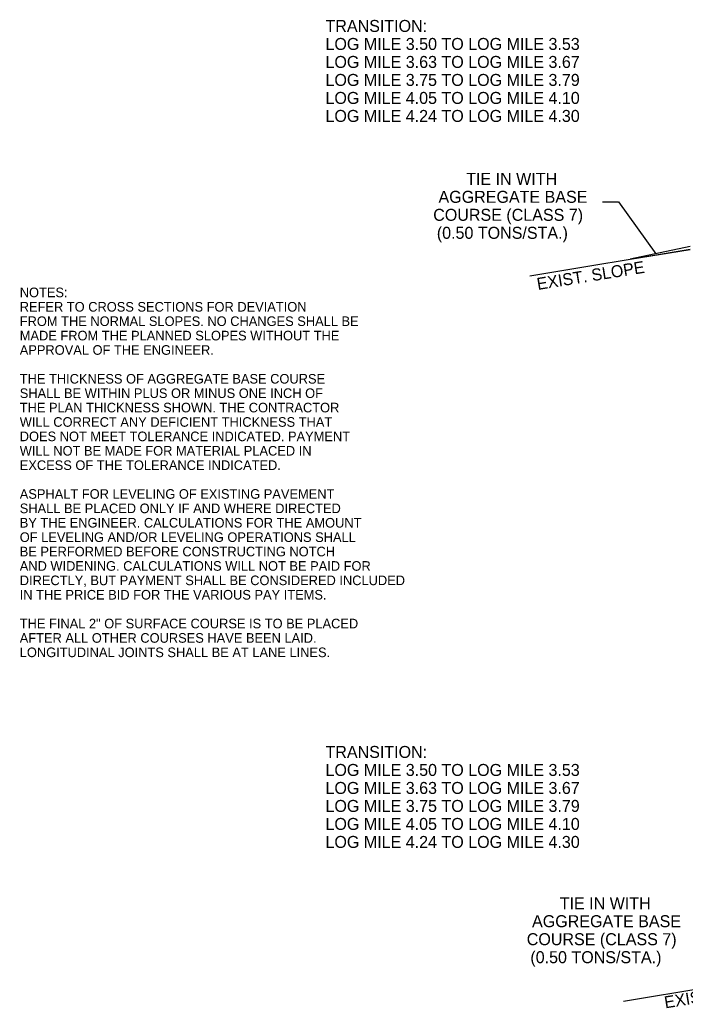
# Model space of a CAD drawing. Extents: x 542112 to 1930787, y -1968972 to 596640.
# Drawn here: x 546302 to 546718, y -1946810 to -1946192 of the extents above; entities that cross this region are included whole.
import ezdxf

# ---------------------------------------------------------------- set-up
doc = ezdxf.new("R2010")
doc.units = 0
doc.layers.add('Default', color=7, linetype='Continuous')
doc.layers.add('R_Draft', color=7, linetype='Continuous')

msp = doc.modelspace()

# ---------------------------------------------------------------- linework, layer by layer
at = {"layer": 'R_Draft'}
for p, q in [((546721.36, -1946335.6), (546621.29, -1946352.28)), ((546721.36, -1946333.9), (546683.86, -1946341.84)), ((546683.86, -1946341.84), (546721.36, -1946335.6)), ((546779.81, -1946789.04), (546679.74, -1946805.71))]:
    msp.add_line(p, q, dxfattribs=at)
msp.add_lwpolyline([(546666.51, -1946305.99), (546676.51, -1946305.99), (546699.84, -1946338.49)], dxfattribs=at)

# ---------------------------------------------------------------- texts
at = {"layer": 'Default'}
for s, p in [('NOTES:', (546302.45, -1946365.52)), ('REFER TO CROSS SECTIONS FOR DEVIATION', (546302.45, -1946374.52)), ('FROM THE NORMAL SLOPES. NO CHANGES SHALL BE', (546302.45, -1946383.52)), ('MADE FROM THE PLANNED SLOPES WITHOUT THE', (546302.45, -1946392.52)), ('APPROVAL OF THE ENGINEER.', (546302.45, -1946401.52)), ('THE THICKNESS OF AGGREGATE BASE COURSE', (546302.45, -1946419.52)), ('SHALL BE WITHIN PLUS OR MINUS ONE INCH OF', (546302.45, -1946428.52)), ('THE PLAN THICKNESS SHOWN. THE CONTRACTOR', (546302.45, -1946437.52)), ('WILL CORRECT ANY DEFICIENT THICKNESS THAT', (546302.45, -1946446.52)), ('DOES NOT MEET TOLERANCE INDICATED. PAYMENT', (546302.45, -1946455.52)), ('WILL NOT BE MADE FOR MATERIAL PLACED IN', (546302.45, -1946464.52)), ('EXCESS OF THE TOLERANCE INDICATED.', (546302.45, -1946473.52)), ('ASPHALT FOR LEVELING OF EXISTING PAVEMENT', (546302.45, -1946491.52)), ('SHALL BE PLACED ONLY IF AND WHERE DIRECTED', (546302.45, -1946500.52)), ('BY THE ENGINEER. CALCULATIONS FOR THE AMOUNT', (546302.45, -1946509.52)), ('OF LEVELING AND/OR LEVELING OPERATIONS SHALL', (546302.45, -1946518.52)), ('BE PERFORMED BEFORE CONSTRUCTING NOTCH', (546302.45, -1946527.52)), ('AND WIDENING. CALCULATIONS WILL NOT BE PAID FOR', (546302.45, -1946536.52)), ('DIRECTLY, BUT PAYMENT SHALL BE CONSIDERED INCLUDED', (546302.45, -1946545.52)), ('IN THE PRICE BID FOR THE VARIOUS PAY ITEMS.', (546302.45, -1946554.52)), ('THE FINAL 2" OF SURFACE COURSE IS TO BE PLACED', (546302.45, -1946572.52)), ('AFTER ALL OTHER COURSES HAVE BEEN LAID.', (546302.45, -1946581.52)), ('LONGITUDINAL JOINTS SHALL BE AT LANE LINES.', (546302.45, -1946590.52))]:
    msp.add_text(s, height=6, dxfattribs=at).set_placement(p)
at = {"layer": 'R_Draft'}
for s, p in [('TRANSITION:', (546493.5, -1946199.71)), ('LOG MILE 3.50 TO LOG MILE 3.53', (546493.5, -1946210.96)), ('LOG MILE 3.63 TO LOG MILE 3.67', (546493.5, -1946222.21)), ('LOG MILE 3.75 TO LOG MILE 3.79', (546493.5, -1946233.46)), ('LOG MILE 4.05 TO LOG MILE 4.10', (546493.5, -1946244.71)), ('LOG MILE 4.24 TO LOG MILE 4.30', (546493.5, -1946255.96)), ('TIE IN WITH ', (546581.43, -1946295.28)), ('AGGREGATE BASE', (546564.12, -1946306.53)), ('COURSE (CLASS 7)', (546560.82, -1946317.78)), ('(0.50 TONS/STA.)', (546563.06, -1946329.03)), ('TRANSITION:', (546493.5, -1946653.54)), ('LOG MILE 3.50 TO LOG MILE 3.53', (546493.5, -1946664.79)), ('LOG MILE 3.63 TO LOG MILE 3.67', (546493.5, -1946676.04)), ('LOG MILE 3.75 TO LOG MILE 3.79', (546493.5, -1946687.29)), ('LOG MILE 4.05 TO LOG MILE 4.10', (546493.5, -1946698.54)), ('LOG MILE 4.24 TO LOG MILE 4.30', (546493.5, -1946709.79)), ('TIE IN WITH ', (546639.88, -1946748.08)), ('AGGREGATE BASE', (546622.58, -1946759.33)), ('COURSE (CLASS 7)', (546619.27, -1946770.58)), ('(0.50 TONS/STA.)', (546621.52, -1946781.83))]:
    msp.add_text(s, height=7.5, dxfattribs=at).set_placement(p)
for p in [(546626.2, -1946361.02), (546705.83, -1946810.12)]:
    msp.add_text('EXIST. SLOPE', height=7.5, rotation=9.15344, dxfattribs=at).set_placement(p)

doc.saveas('drawing.dxf')
